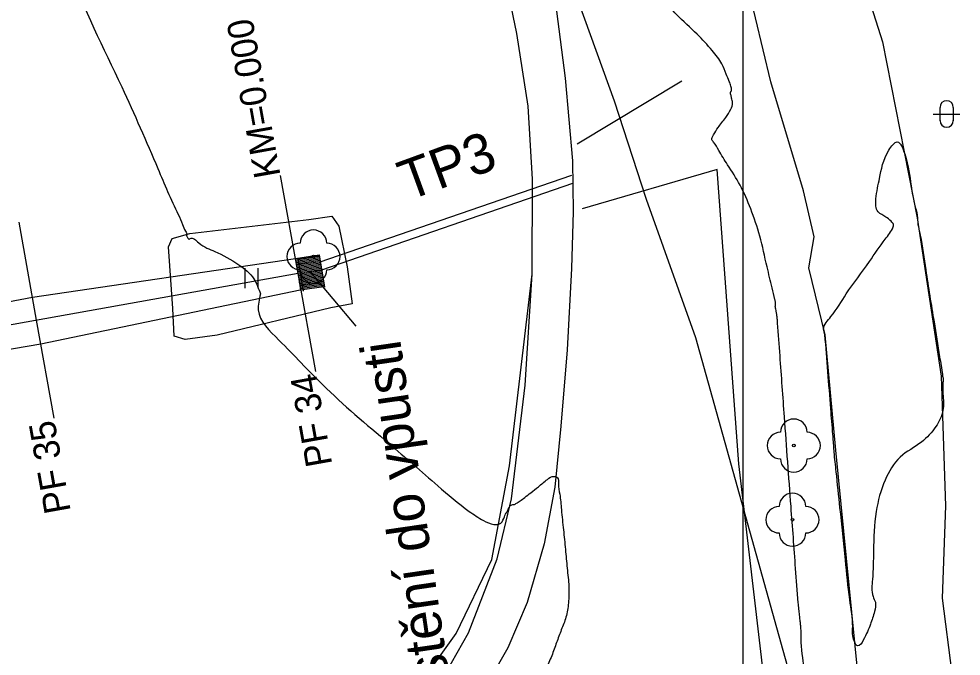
# Model space of a CAD drawing. Extents: x -478102 to -473059, y -1117705 to -1114104.
# Drawn here: x -476236.8 to -476165.9, y -1117060.7 to -1117012.7 of the extents above; entities that cross this region are included whole.
import ezdxf

# ---------------------------------------------------------------- set-up
doc = ezdxf.new("R2010")
doc.units = 0
for name, color, linetype in [('cestn___p____kop_n__vrh', 7, 'Continuous'), ('el_vedeni__VN', 7, 'Continuous'), ('HladinaVodnihoToku', 7, 'Continuous'), ('HranaTerennihoUtvaru', 7, 'Continuous'), ('ObPÚ', 7, 'Continuous'), ('POLYGONY_SITUACE_PF', 7, 'Continuous'), ('POLYGONY_SITUACE_PF_POPISY', 7, 'Continuous'), ('POLYGONY_SITUACE_PO', 7, 'Continuous'), ('PopisneZnackyKultura', 7, 'Continuous'), ('RozhraniKultur', 7, 'Continuous'), ('RozhraniVozovky', 7, 'Continuous'), ('TP _navrh', 7, 'Continuous'), ('Vrstevnice_vedlejsi', 7, 'Continuous'), ('ZnackyStromu', 7, 'Continuous')]:
    doc.layers.add(name, color=color, linetype=linetype)

msp = doc.modelspace()

# ---------------------------------------------------------------- linework, layer by layer
for p, q in [((-476214.237, -1117031.047), (-476195.209, -1117024.475)), ((-476214.041, -1117031.614), (-476195.148, -1117025.088)), ((-476216.022, -1117030.757), (-476214.226, -1117030.492)), ((-476216.007, -1117030.856), (-476214.211, -1117030.591)), ((-476215.993, -1117030.955), (-476214.197, -1117030.69)), ((-476215.978, -1117031.054), (-476214.182, -1117030.789)), ((-476215.964, -1117031.153), (-476214.167, -1117030.888)), ((-476215.949, -1117031.252), (-476214.153, -1117030.986)), ((-476215.934, -1117031.351), (-476214.138, -1117031.085)), ((-476215.92, -1117031.449), (-476214.124, -1117031.184)), ((-476215.905, -1117031.548), (-476214.109, -1117031.283)), ((-476215.891, -1117031.647), (-476214.094, -1117031.382)), ((-476215.876, -1117031.746), (-476214.08, -1117031.481)), ((-476215.861, -1117031.845), (-476214.065, -1117031.58)), ((-476215.847, -1117031.944), (-476214.051, -1117031.679)), ((-476215.832, -1117032.043), (-476214.036, -1117031.778)), ((-476215.818, -1117032.142), (-476214.021, -1117031.877)), ((-476215.803, -1117032.241), (-476214.007, -1117031.976)), ((-476215.788, -1117032.34), (-476213.992, -1117032.075)), ((-476215.774, -1117032.439), (-476213.978, -1117032.174)), ((-476214.944, -1117031.754), (-476211.472, -1117035.864)), ((-476215.759, -1117032.538), (-476213.963, -1117032.273)), ((-476215.745, -1117032.637), (-476213.948, -1117032.371)), ((-476215.73, -1117032.736), (-476213.934, -1117032.47)), ((-476215.715, -1117032.834), (-476213.919, -1117032.569)), ((-476215.701, -1117032.933), (-476213.905, -1117032.668)), ((-476215.686, -1117033.032), (-476213.89, -1117032.767)), ((-476215.671, -1117033.131), (-476213.875, -1117032.866))]:
    msp.add_line(p, q)
at = {"layer": 'cestn___p____kop_n__vrh'}
for p, q in [((-476215.836, -1117030.726), (-476215.435, -1117033.234)), ((-476215.823, -1117030.81), (-476214.213, -1117030.571)), ((-476214.226, -1117030.492), (-476213.83, -1117032.921))]:
    msp.add_line(p, q, dxfattribs=at)
msp.add_lwpolyline([(-476182.335, -1117180.282), (-476602.335, -1117180.282), (-476602.335, -1116586.282), (-476182.335, -1116586.282)], close=True, dxfattribs=at)
at = {"layer": 'el_vedeni__VN'}
for points in [[(-476235.819, -1117033.671), (-476216.022, -1117030.757)], [(-476235.187, -1117037.196), (-476215.671, -1117033.131)], [(-476255.471, -1117037.386), (-476235.819, -1117033.671)], [(-476254.906, -1117040.545), (-476235.187, -1117037.196)]]:
    msp.add_lwpolyline(points, dxfattribs=at)
at = {"layer": 'HladinaVodnihoToku'}
for points in [[(-476230.693, -1116889.189), (-476228.825, -1116902.805), (-476226.997, -1116912.134), (-476222.681, -1116925.337), (-476220.229, -1116932.601), (-476216.175, -1116939.113), (-476212.858, -1116942.625), (-476205.972, -1116953.141), (-476203.252, -1116954.891), (-476199.271, -1116960.088), (-476194.333, -1116968.049), (-476189.738, -1116975.171), (-476186.133, -1116982.38), (-476183.739, -1116986.147), (-476182.486, -1116989.695), (-476180.477, -1116994.376), (-476178.089, -1116997.289), (-476174.589, -1117005.739), (-476171.819, -1117014.439), (-476169.214, -1117027.705), (-476167.401, -1117039.631), (-476167.078, -1117049.404), (-476167.323, -1117056.351), (-476165.871, -1117067.691)], [(-476165.052, -1117135.383), (-476166.552, -1117122.432), (-476167.831, -1117116.835), (-476168.995, -1117106.978), (-476170.029, -1117098.738), (-476170.701, -1117095.145), (-476170.746, -1117087.056), (-476171.949, -1117074.832), (-476173.391, -1117070.652), (-476173.059, -1117068.741), (-476173.366, -1117065.264), (-476174.142, -1117057.395), (-476175.337, -1117045.193), (-476176.15, -1117036.518), (-476177.362, -1117031.476), (-476176.964, -1117029.141), (-476177.777, -1117025.659), (-476180.222, -1117017.465), (-476181.969, -1117010.204)]]:
    msp.add_lwpolyline(points, dxfattribs=at)
at = {"layer": 'HranaTerennihoUtvaru'}
for points in [[(-476186.94, -1117017.41), (-476194.82, -1117022.15)], [(-476178.08, -1117085.22), (-476182.65, -1117046.23), (-476184.28, -1117024.06), (-476194.45, -1117027.03)]]:
    msp.add_lwpolyline(points, dxfattribs=at)
at = {"layer": 'ObPÚ'}
msp.add_lwpolyline([(-476159.5, -1117192.77), (-476224.13, -1117203.13), (-476225.41, -1117191.08), (-476226.67, -1117162.34), (-476231.32, -1117146.23), (-476236.27, -1117130.89), (-476197.93, -1117123.85), (-476173.05, -1117118.52), (-476175.07, -1117075.48), (-476185.89, -1117036.74), (-476189.59, -1117026.33), (-476192, -1117018.92), (-476203.93, -1116985.93)], dxfattribs=at)
at = {"layer": 'POLYGONY_SITUACE_PF'}
for points in [[(-476214.499, -1117039.265), (-476215.821, -1117031.882), (-476217.143, -1117024.5)], [(-476234.186, -1117042.79), (-476235.508, -1117035.407), (-476236.83, -1117028.025)]]:
    msp.add_lwpolyline(points, dxfattribs=at)
at = {"layer": 'POLYGONY_SITUACE_PO'}
msp.add_lwpolyline([(-476215.821, -1117031.882), (-476278.268, -1117043.064)], dxfattribs=at)
at = {"layer": 'PopisneZnackyKultura'}
for p, q in [((-476167.506, -1117019.386), (-476167.506, -1117020.386)), ((-476166.506, -1117019.386), (-476166.506, -1117020.386)), ((-476168.006, -1117019.886), (-476166.006, -1117019.886)), ((-476219.82, -1117032.999), (-476219.82, -1117031.499)), ((-476218.82, -1117032.999), (-476218.82, -1117031.499))]:
    msp.add_line(p, q, dxfattribs=at)
for centre, start, end in [((-476166.998, -1117019.378), 0, 180), ((-476166.998, -1117020.378), 180, 0)]:
    msp.add_arc(centre, 0.5, start, end, dxfattribs=at)
at = {"layer": 'RozhraniKultur'}
msp.add_lwpolyline([(-476225.593, -1117029.883), (-476225.296, -1117029.248), (-476223.977, -1117028.88), (-476215.019, -1117027.833), (-476213.274, -1117027.562), (-476212.764, -1117028.324), (-476212.138, -1117031.392), (-476211.741, -1117034.183), (-476213.357, -1117034.486), (-476221.906, -1117036.536), (-476224.324, -1117036.868), (-476225.145, -1117036.604), (-476225.253, -1117034.523)], close=True, dxfattribs=at)
msp.add_lwpolyline([(-476326.155, -1117118.092), (-476289.536, -1117114.347), (-476268.698, -1117113.377), (-476254.616, -1117112.232), (-476253.368, -1117111.396), (-476254.26, -1117105.118), (-476253.444, -1117098.834), (-476252.052, -1117092.56), (-476249.674, -1117089.102), (-476247.41, -1117085.365), (-476243.552, -1117082.341), (-476239.642, -1117080.005), (-476234.251, -1117077.288), (-476223.428, -1117073.653), (-476215.212, -1117070.499), (-476211.753, -1117068.101), (-476207.257, -1117063.687), (-476203.922, -1117059.007), (-476201.245, -1117053.431), (-476199.908, -1117046.384), (-476198.206, -1117031.932)], dxfattribs=at)
at = {"layer": 'RozhraniVozovky'}
for points in [[(-476247.93, -1117088.545), (-476245.077, -1117085.472), (-476240.982, -1117082.296), (-476238.115, -1117080.557), (-476233.979, -1117078.501), (-476225.492, -1117075.329), (-476219.895, -1117073.227), (-476215.189, -1117071.158), (-476211.766, -1117069.21), (-476209.272, -1117067.263), (-476206.779, -1117064.716), (-476204.692, -1117061.981), (-476203, -1117058.967), (-476200.833, -1117053.375), (-476199.75, -1117048.873), (-476198.727, -1117040.3), (-476198.206, -1117031.932), (-476198.165, -1117024.787), (-476198.499, -1117019.299), (-476199.36, -1117013.806), (-476200.192, -1117009.793)], [(-476196.364, -1117012.13), (-476195.729, -1117017.189), (-476195.176, -1117023.395), (-476195.112, -1117027.233), (-476195.235, -1117031.513), (-476195.559, -1117037.637), (-476196.033, -1117043.394), (-476196.483, -1117047.979), (-476197.306, -1117052.252), (-476198.582, -1117056.674), (-476200.039, -1117060.081), (-476202.244, -1117063.965), (-476204.836, -1117067.407), (-476207.857, -1117070.218), (-476210.834, -1117072.302), (-476213.828, -1117073.953), (-476223.737, -1117077.95), (-476233.774, -1117081.756), (-476236.901, -1117083.35), (-476239.761, -1117085.24), (-476241.85, -1117086.802)]]:
    msp.add_lwpolyline(points, dxfattribs=at)
at = {"layer": 'Vrstevnice_vedlejsi'}
for points in [[(-476316.243, -1116908.48), (-476314.561, -1116908.998), (-476313.123, -1116909.665), (-476311.928, -1116910.479), (-476310.975, -1116911.441), (-476307.447, -1116912.926), (-476301.342, -1116914.935), (-476292.661, -1116917.468), (-476286.431, -1116920.344), (-476282.653, -1116923.565), (-476281.326, -1116927.13), (-476278.825, -1116928.622), (-476275.148, -1116928.043), (-476270.296, -1116925.391), (-476267.359, -1116923.353), (-476266.337, -1116921.926), (-476267.229, -1116921.113), (-476266.831, -1116920.277), (-476265.141, -1116919.419), (-476262.159, -1116918.539), (-476258.731, -1116917.573), (-476254.857, -1116916.522), (-476250.536, -1116915.385), (-476247.506, -1116914.708), (-476245.767, -1116914.49), (-476245.318, -1116914.73), (-476244.967, -1116914.931), (-476244.714, -1116915.09), (-476244.558, -1116915.209), (-476244.297, -1116915.426), (-476243.929, -1116915.74), (-476243.455, -1116916.152), (-476242.992, -1116916.618), (-476242.539, -1116917.137), (-476242.097, -1116917.711), (-476241.648, -1116918.268), (-476241.19, -1116918.809), (-476240.724, -1116919.335), (-476240.357, -1116919.802), (-476240.09, -1116920.212), (-476239.921, -1116920.565), (-476239.776, -1116920.901), (-476239.653, -1116921.22), (-476239.554, -1116921.522), (-476239.275, -1116922.323), (-476238.817, -1116923.622), (-476238.18, -1116925.419), (-476237.671, -1116926.892), (-476237.289, -1116928.04), (-476237.035, -1116928.865), (-476237.012, -1116929.601), (-476237.222, -1116930.251), (-476237.665, -1116930.812), (-476238.042, -1116931.305), (-476238.354, -1116931.728), (-476238.601, -1116932.083), (-476239.32, -1116932.842), (-476240.511, -1116934.008), (-476242.173, -1116935.579), (-476243.89, -1116939.165), (-476245.66, -1116944.767), (-476247.485, -1116952.383), (-476247.667, -1116959.217), (-476246.206, -1116965.267), (-476243.103, -1116970.535), (-476240.745, -1116976.442), (-476239.133, -1116982.988), (-476238.266, -1116990.175), (-476237.639, -1116995.076), (-476237.25, -1116997.694), (-476237.099, -1116998.028), (-476236.956, -1116998.362), (-476236.818, -1116998.698), (-476236.687, -1116999.033), (-476236.643, -1116999.341), (-476236.684, -1116999.621), (-476236.813, -1116999.873), (-476235.592, -1117002.993), (-476233.023, -1117008.983), (-476229.104, -1117017.842), (-476226.381, -1117023.996), (-476224.854, -1117027.447), (-476224.521, -1117028.193), (-476224.304, -1117028.701), (-476224.204, -1117028.973), (-476224.22, -1117029.007), (-476224.213, -1117029.062), (-476224.183, -1117029.137), (-476224.131, -1117029.234), (-476224.075, -1117029.288), (-476224.014, -1117029.297), (-476223.948, -1117029.262), (-476223.307, -1117029.574), (-476222.09, -1117030.231), (-476220.296, -1117031.233), (-476219.154, -1117032.301), (-476218.662, -1117033.435)], [(-476179.724, -1117035.627), (-476179.75, -1117035.303), (-476179.782, -1117035.021), (-476179.82, -1117034.78), (-476179.865, -1117034.582), (-476179.89, -1117034.419), (-476179.894, -1117034.292), (-476179.878, -1117034.199), (-476179.879, -1117034.093), (-476179.896, -1117033.973), (-476179.929, -1117033.839), (-476180.135, -1117032.979), (-476180.515, -1117031.393), (-476181.068, -1117029.081), (-476181.748, -1117027.028), (-476182.554, -1117025.234), (-476183.488, -1117023.699), (-476184.151, -1117022.618), (-476184.543, -1117021.993), (-476184.665, -1117021.823), (-476184.551, -1117021.459), (-476184.202, -1117020.899), (-476183.616, -1117020.145), (-476183.252, -1117019.523), (-476183.11, -1117019.034), (-476183.19, -1117018.678), (-476183.244, -1117018.432), (-476183.271, -1117018.296), (-476183.272, -1117018.269), (-476183.261, -1117018.232), (-476183.237, -1117018.185), (-476183.201, -1117018.126), (-476183.188, -1117018.039), (-476183.199, -1117017.923), (-476183.234, -1117017.779), (-476183.365, -1117017.428), (-476183.592, -1117016.87), (-476183.916, -1117016.106), (-476184.647, -1117015.105), (-476185.785, -1117013.867), (-476187.33, -1117012.392), (-476188.388, -1117011.262), (-476188.958, -1117010.478), (-476189.041, -1117010.039), (-476189.106, -1117009.636), (-476189.153, -1117009.267), (-476189.182, -1117008.935), (-476189.557, -1117008.114), (-476190.278, -1117006.805), (-476191.346, -1117005.008), (-476192.127, -1117003.633), (-476192.621, -1117002.68), (-476192.828, -1117002.148), (-476193.262, -1117001.482), (-476193.923, -1117000.684), (-476194.811, -1116999.752), (-476195.507, -1116998.877), (-476196.011, -1116998.058), (-476196.323, -1116997.295), (-476196.58, -1116996.639), (-476196.782, -1116996.088), (-476196.93, -1116995.644), (-476197.398, -1116994.17), (-476198.187, -1116991.667), (-476199.296, -1116988.134), (-476200.094, -1116985.612), (-476200.58, -1116984.1), (-476200.756, -1116983.599), (-476200.905, -1116983.191), (-476201.028, -1116982.876), (-476201.124, -1116982.653), (-476201.204, -1116982.463), (-476201.268, -1116982.305), (-476201.315, -1116982.181), (-476202.111, -1116980.963), (-476203.654, -1116978.651), (-476205.945, -1116975.246), (-476207.511, -1116972.904), (-476208.351, -1116971.625), (-476208.466, -1116971.41), (-476208.609, -1116971.129), (-476208.78, -1116970.784), (-476208.979, -1116970.373), (-476209.684, -1116969.095), (-476210.895, -1116966.948), (-476212.612, -1116963.934), (-476214.062, -1116961.433), (-476215.245, -1116959.445), (-476216.162, -1116957.97), (-476216.798, -1116956.955), (-476217.154, -1116956.399), (-476217.228, -1116956.303), (-476217.294, -1116956.22), (-476217.349, -1116956.15), (-476217.396, -1116956.094), (-476218.104, -1116955.211), (-476219.474, -1116953.504)], [(-476176.161, -1117036.513), (-476175.718, -1117042.074), (-476175.564, -1117044.01), (-476175.479, -1117045.102), (-476175.461, -1117045.349), (-476175.311, -1117046.825), (-476175.028, -1117049.53), (-476174.614, -1117053.465), (-476174.295, -1117056.457), (-476174.071, -1117058.506), (-476173.943, -1117059.613), (-476173.677, -1117059.948), (-476173.274, -1117059.512), (-476172.734, -1117058.304), (-476172.431, -1117057.352), (-476172.366, -1117056.656), (-476172.538, -1117056.216), (-476172.585, -1117054.93), (-476172.507, -1117052.798), (-476172.304, -1117049.82), (-476171.633, -1117047.459), (-476170.492, -1117045.715), (-476168.883, -1117044.587), (-476167.811, -1117043.42), (-476167.276, -1117042.212), (-476167.277, -1117040.965), (-476167.282, -1117040.123), (-476167.288, -1117039.686), (-476167.298, -1117039.655), (-476167.306, -1117039.615), (-476167.313, -1117039.564), (-476167.319, -1117039.504), (-476167.531, -1117038.16), (-476167.948, -1117035.533), (-476168.572, -1117031.623), (-476168.988, -1117029.013), (-476169.197, -1117027.703), (-476169.197, -1117027.693), (-476169.357, -1117026.885), (-476169.677, -1117025.278), (-476170.156, -1117022.874), (-476170.711, -1117021.98), (-476171.342, -1117022.599), (-476172.05, -1117024.729), (-476172.323, -1117026.279), (-476172.161, -1117027.249), (-476171.565, -1117027.64), (-476171.177, -1117027.959), (-476170.999, -1117028.206), (-476171.029, -1117028.383), (-476171.632, -1117029.313), (-476172.807, -1117030.997), (-476174.556, -1117033.436), (-476175.706, -1117035.133), (-476176.257, -1117036.087), (-476176.161, -1117036.513)], [(-476218.662, -1117033.435), (-476218.822, -1117034.635), (-476217.263, -1117036.911), (-476213.986, -1117040.265), (-476208.992, -1117044.695), (-476205.309, -1117047.877), (-476202.938, -1117049.809), (-476201.877, -1117050.493), (-476201.083, -1117050.788), (-476200.555, -1117050.695), (-476200.293, -1117050.212), (-476200.099, -1117049.847), (-476199.974, -1117049.597), (-476199.917, -1117049.464), (-476199.835, -1117049.37), (-476199.726, -1117049.313), (-476199.592, -1117049.295), (-476199.387, -1117049.198), (-476199.112, -1117049.021), (-476198.765, -1117048.765), (-476198.307, -1117048.409), (-476197.736, -1117047.953), (-476197.054, -1117047.397), (-476196.575, -1117047.173), (-476196.299, -1117047.28), (-476196.227, -1117047.719), (-476196.128, -1117048.519), (-476196.001, -1117049.68), (-476195.846, -1117051.202), (-476195.702, -1117052.674), (-476195.567, -1117054.097), (-476195.442, -1117055.471), (-476195.474, -1117056.701), (-476195.663, -1117057.787), (-476196.008, -1117058.731), (-476196.365, -1117059.696), (-476196.731, -1117060.685), (-476197.109, -1117061.695), (-476197.123, -1117063.752), (-476196.775, -1117066.855), (-476196.063, -1117071.005), (-476195.366, -1117074.361), (-476194.682, -1117076.923), (-476194.013, -1117078.692), (-476193.219, -1117080.86), (-476192.302, -1117083.427), (-476191.26, -1117086.392), (-476189.817, -1117090.625), (-476187.973, -1117096.125), (-476185.729, -1117102.894), (-476183.735, -1117108.045), (-476181.992, -1117111.578), (-476180.498, -1117113.494), (-476178.823, -1117115.088), (-476176.965, -1117116.361), (-476174.925, -1117117.312), (-476173.551, -1117118.042), (-476172.843, -1117118.55), (-476172.8, -1117118.837), (-476172.731, -1117119.351), (-476172.637, -1117120.093), (-476172.517, -1117121.062), (-476172.381, -1117123.052), (-476172.229, -1117126.063), (-476172.059, -1117130.096), (-476171.954, -1117132.864), (-476171.913, -1117134.367), (-476171.937, -1117134.606), (-476172.55, -1117135.185), (-476173.752, -1117136.105), (-476175.544, -1117137.365), (-476176.609, -1117138.711), (-476176.875, -1117139.506)], [(-476167.154, -1117137.424), (-476167.161, -1117137.225), (-476167.247, -1117136.247), (-476167.406, -1117134.768), (-476167.64, -1117132.789), (-476168.012, -1117130.045), (-476168.521, -1117126.535), (-476169.167, -1117122.259), (-476169.669, -1117119.115), (-476170.025, -1117117.1), (-476170.236, -1117116.217), (-476170.442, -1117115.129), (-476170.643, -1117113.838), (-476170.838, -1117112.343), (-476171.127, -1117110.728), (-476171.51, -1117108.993), (-476171.987, -1117107.138), (-476172.343, -1117105.532), (-476172.58, -1117104.177), (-476172.697, -1117103.072), (-476172.807, -1117102.176), (-476172.909, -1117101.489), (-476173.004, -1117101.011), (-476173.299, -1117099.062), (-476173.794, -1117095.642), (-476174.488, -1117090.75), (-476174.951, -1117087.207), (-476175.181, -1117085.013), (-476175.18, -1117084.167), (-476175.236, -1117083.188), (-476175.348, -1117082.077), (-476175.517, -1117080.833), (-476175.674, -1117079.86), (-476175.821, -1117079.16), (-476175.956, -1117078.731), (-476176.254, -1117076.34), (-476176.715, -1117071.985), (-476177.338, -1117065.667), (-476177.752, -1117061.381), (-476177.957, -1117059.126), (-476177.954, -1117058.902), (-476177.964, -1117058.642), (-476177.989, -1117058.344), (-476178.028, -1117058.009), (-476178.071, -1117057.621), (-476178.119, -1117057.181), (-476178.171, -1117056.687), (-476178.37, -1117054.109), (-476178.715, -1117049.446), (-476179.207, -1117042.699), (-476179.543, -1117038.092), (-476179.724, -1117035.627)]]:
    msp.add_spline(points, degree=3, dxfattribs=at)
at = {"layer": 'ZnackyStromu'}
for centre in [(-476214.667, -1117030.614), (-476178.506, -1117044.853), (-476178.606, -1117050.437)]:
    msp.add_circle(centre, 0.1, dxfattribs=at)
for centre, start, end in [((-476214.667, -1117029.614), 0, 180), ((-476215.667, -1117030.614), 90, 270), ((-476213.667, -1117030.614), 270, 90), ((-476214.667, -1117031.614), 180, 0), ((-476178.506, -1117043.853), 0, 180), ((-476179.506, -1117044.853), 90, 270), ((-476177.506, -1117044.853), 270, 90), ((-476178.506, -1117045.853), 180, 0), ((-476178.606, -1117049.437), 0, 180), ((-476179.606, -1117050.437), 90, 270), ((-476177.606, -1117050.437), 270, 90), ((-476178.606, -1117051.437), 180, 0)]:
    msp.add_arc(centre, 1, start, end, dxfattribs=at)

# ---------------------------------------------------------------- texts
at = {"layer": 'POLYGONY_SITUACE_PF_POPISY'}
for s, p in [('KM=0.000', (-476217.14, -1117024.512)), ('PF 34', (-476213.245, -1117046.269)), ('PF 35', (-476232.931, -1117049.794))]:
    msp.add_text(s, height=1.9765, rotation=100.15203, dxfattribs=at).set_placement(p)
at = {"layer": 'TP _navrh'}
for s, rotation, p in [('TP3', 20.06066, (-476207.571, -1117026.44)), ('zaústění do vpusti', 98.28402, (-476203.492, -1117068.783))]:
    msp.add_text(s, height=3, rotation=rotation, dxfattribs=at).set_placement(p)

doc.saveas('drawing.dxf')
